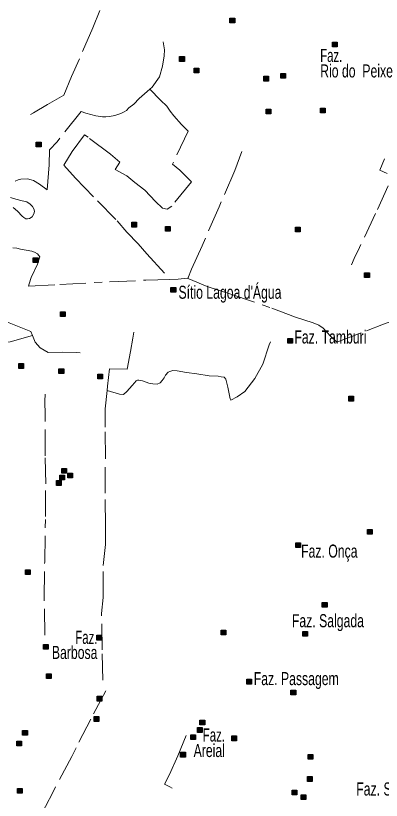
# Model space of a CAD drawing. Extents: x 445.6 to 500, y 8618.1 to 8673.4.
# Drawn here: x 480.73 to 485.21, y 8658.81 to 8668.42 of the extents above; entities that cross this region are included whole.
import ezdxf
from ezdxf.enums import TextEntityAlignment as Align

# ---------------------------------------------------------------- set-up
doc = ezdxf.new("R2010")
doc.units = 0
doc.header["$LTSCALE"] = 0.064
doc.linetypes.add('DOT_DASHED', pattern=[7.7, 5, -1.2, 0.3, -1.2])
doc.layers.add('2', color=7, linetype='Continuous', lineweight=25)
doc.layers.add('22', color=7, linetype='DOT_DASHED', lineweight=13)
doc.layers.add('61', color=7, linetype='Continuous')

msp = doc.modelspace()

# ---------------------------------------------------------------- hatches: boundary and pattern name
at = {"layer": '2'}
for points in [[(483.3572, 8668.3929), (483.4152, 8668.3929), (483.4152, 8668.3349), (483.3572, 8668.3349)], [(484.6131, 8668.0979), (484.6711, 8668.0979), (484.6711, 8668.0399), (484.6131, 8668.0399)], [(482.7407, 8667.9212), (482.7987, 8667.9212), (482.7987, 8667.8632), (482.7407, 8667.8632)], [(482.9197, 8667.7822), (482.9777, 8667.7822), (482.9777, 8667.7242), (482.9197, 8667.7242)], [(483.771, 8667.6806), (483.829, 8667.6806), (483.829, 8667.6226), (483.771, 8667.6226)], [(483.9804, 8667.7145), (484.0384, 8667.7145), (484.0384, 8667.6565), (483.9804, 8667.6565)], [(483.8014, 8667.2774), (483.8594, 8667.2774), (483.8594, 8667.2194), (483.8014, 8667.2194)], [(484.4646, 8667.2911), (484.5226, 8667.2911), (484.5226, 8667.2331), (484.4646, 8667.2331)], [(480.9857, 8666.8743), (481.0437, 8666.8743), (481.0437, 8666.8163), (480.9857, 8666.8163)], [(482.1561, 8665.8922), (482.2141, 8665.8922), (482.2141, 8665.8342), (482.1561, 8665.8342)], [(482.5671, 8665.8413), (482.6251, 8665.8413), (482.6251, 8665.7833), (482.5671, 8665.7833)], [(484.1581, 8665.8345), (484.2161, 8665.8345), (484.2161, 8665.7765), (484.1581, 8665.7765)], [(480.949, 8665.4585), (481.007, 8665.4585), (481.007, 8665.4005), (480.949, 8665.4005)], [(485.0065, 8665.2722), (485.0645, 8665.2722), (485.0645, 8665.2142), (485.0065, 8665.2142)], [(482.6347, 8665.0925), (482.6927, 8665.0925), (482.6927, 8665.0345), (482.6347, 8665.0345)], [(481.2812, 8664.7945), (481.3392, 8664.7945), (481.3392, 8664.7365), (481.2812, 8664.7365)], [(484.0668, 8664.4691), (484.1248, 8664.4691), (484.1248, 8664.4111), (484.0668, 8664.4111)], [(480.77, 8664.1608), (480.828, 8664.1608), (480.828, 8664.1028), (480.77, 8664.1028)], [(481.2632, 8664.0972), (481.3212, 8664.0972), (481.3212, 8664.0392), (481.2632, 8664.0392)], [(481.7384, 8664.032), (481.7964, 8664.032), (481.7964, 8663.974), (481.7384, 8663.974)], [(484.8128, 8663.7609), (484.8708, 8663.7609), (484.8708, 8663.7029), (484.8128, 8663.7029)], [(481.2967, 8662.8767), (481.3547, 8662.8767), (481.3547, 8662.8187), (481.2967, 8662.8187)], [(481.2731, 8662.7954), (481.3311, 8662.7954), (481.3311, 8662.7374), (481.2731, 8662.7374)], [(481.371, 8662.8191), (481.429, 8662.8191), (481.429, 8662.7611), (481.371, 8662.7611)], [(481.2325, 8662.7276), (481.2905, 8662.7276), (481.2905, 8662.6696), (481.2325, 8662.6696)], [(485.0427, 8662.1296), (485.1007, 8662.1296), (485.1007, 8662.0716), (485.0427, 8662.0716)], [(484.1636, 8661.9648), (484.2216, 8661.9648), (484.2216, 8661.9068), (484.1636, 8661.9068)], [(480.8536, 8661.6359), (480.9116, 8661.6359), (480.9116, 8661.5779), (480.8536, 8661.5779)], [(484.4878, 8661.2364), (484.5458, 8661.2364), (484.5458, 8661.1784), (484.4878, 8661.1784)], [(481.7251, 8660.833), (481.7831, 8660.833), (481.7831, 8660.775), (481.7251, 8660.775)], [(483.2491, 8660.8976), (483.3071, 8660.8976), (483.3071, 8660.8396), (483.2491, 8660.8396)], [(484.248, 8660.8807), (484.306, 8660.8807), (484.306, 8660.8227), (484.248, 8660.8227)], [(481.0732, 8660.7212), (481.1312, 8660.7212), (481.1312, 8660.6632), (481.0732, 8660.6632)], [(481.1103, 8660.3621), (481.1683, 8660.3621), (481.1683, 8660.3041), (481.1103, 8660.3041)], [(483.5641, 8660.2937), (483.6221, 8660.2937), (483.6221, 8660.2357), (483.5641, 8660.2357)], [(484.1046, 8660.1616), (484.1626, 8660.1616), (484.1626, 8660.1036), (484.1046, 8660.1036)], [(481.7296, 8660.086), (481.7876, 8660.086), (481.7876, 8660.028), (481.7296, 8660.028)], [(481.6955, 8659.8367), (481.7535, 8659.8367), (481.7535, 8659.7787), (481.6955, 8659.7787)], [(482.9901, 8659.793), (483.0481, 8659.793), (483.0481, 8659.735), (482.9901, 8659.735)], [(482.9597, 8659.7015), (483.0177, 8659.7015), (483.0177, 8659.6435), (482.9597, 8659.6435)], [(480.8185, 8659.6673), (480.8765, 8659.6673), (480.8765, 8659.6093), (480.8185, 8659.6093)], [(482.8786, 8659.6135), (482.9366, 8659.6135), (482.9366, 8659.5555), (482.8786, 8659.5555)], [(483.3785, 8659.5999), (483.4365, 8659.5999), (483.4365, 8659.5419), (483.3785, 8659.5419)], [(480.7475, 8659.5351), (480.8055, 8659.5351), (480.8055, 8659.4771), (480.7475, 8659.4771)], [(482.7536, 8659.4), (482.8116, 8659.4), (482.8116, 8659.342), (482.7536, 8659.342)], [(484.3142, 8659.3729), (484.3722, 8659.3729), (484.3722, 8659.3149), (484.3142, 8659.3149)], [(484.3074, 8659.1019), (484.3654, 8659.1019), (484.3654, 8659.0439), (484.3074, 8659.0439)], [(480.7543, 8658.9558), (480.8123, 8658.9558), (480.8123, 8658.8978), (480.7543, 8658.8978)], [(484.1183, 8658.9359), (484.1763, 8658.9359), (484.1763, 8658.8779), (484.1183, 8658.8779)], [(484.2297, 8658.8783), (484.2877, 8658.8783), (484.2877, 8658.8203), (484.2297, 8658.8203)]]:
    msp.add_hatch(color=256, dxfattribs=at).paths.add_polyline_path(points)

# ---------------------------------------------------------------- linework, layer by layer
for points in [[(483.3572, 8668.3929), (483.4152, 8668.3929), (483.4152, 8668.3349), (483.3572, 8668.3349)], [(484.6131, 8668.0979), (484.6711, 8668.0979), (484.6711, 8668.0399), (484.6131, 8668.0399)], [(482.7407, 8667.9212), (482.7987, 8667.9212), (482.7987, 8667.8632), (482.7407, 8667.8632)], [(482.9197, 8667.7822), (482.9777, 8667.7822), (482.9777, 8667.7242), (482.9197, 8667.7242)], [(483.771, 8667.6806), (483.829, 8667.6806), (483.829, 8667.6226), (483.771, 8667.6226)], [(483.9804, 8667.7145), (484.0384, 8667.7145), (484.0384, 8667.6565), (483.9804, 8667.6565)], [(483.8014, 8667.2774), (483.8594, 8667.2774), (483.8594, 8667.2194), (483.8014, 8667.2194)], [(484.4646, 8667.2911), (484.5226, 8667.2911), (484.5226, 8667.2331), (484.4646, 8667.2331)], [(480.9857, 8666.8743), (481.0437, 8666.8743), (481.0437, 8666.8163), (480.9857, 8666.8163)], [(482.1561, 8665.8922), (482.2141, 8665.8922), (482.2141, 8665.8342), (482.1561, 8665.8342)], [(482.5671, 8665.8413), (482.6251, 8665.8413), (482.6251, 8665.7833), (482.5671, 8665.7833)], [(484.1581, 8665.8345), (484.2161, 8665.8345), (484.2161, 8665.7765), (484.1581, 8665.7765)], [(480.949, 8665.4585), (481.007, 8665.4585), (481.007, 8665.4005), (480.949, 8665.4005)], [(485.0065, 8665.2722), (485.0645, 8665.2722), (485.0645, 8665.2142), (485.0065, 8665.2142)], [(482.6347, 8665.0925), (482.6927, 8665.0925), (482.6927, 8665.0345), (482.6347, 8665.0345)], [(481.2812, 8664.7945), (481.3392, 8664.7945), (481.3392, 8664.7365), (481.2812, 8664.7365)], [(484.0668, 8664.4691), (484.1248, 8664.4691), (484.1248, 8664.4111), (484.0668, 8664.4111)], [(480.77, 8664.1608), (480.828, 8664.1608), (480.828, 8664.1028), (480.77, 8664.1028)], [(481.2632, 8664.0972), (481.3212, 8664.0972), (481.3212, 8664.0392), (481.2632, 8664.0392)], [(481.7384, 8664.032), (481.7964, 8664.032), (481.7964, 8663.974), (481.7384, 8663.974)], [(484.8128, 8663.7609), (484.8708, 8663.7609), (484.8708, 8663.7029), (484.8128, 8663.7029)], [(481.2967, 8662.8767), (481.3547, 8662.8767), (481.3547, 8662.8187), (481.2967, 8662.8187)], [(481.2731, 8662.7954), (481.3311, 8662.7954), (481.3311, 8662.7374), (481.2731, 8662.7374)], [(481.371, 8662.8191), (481.429, 8662.8191), (481.429, 8662.7611), (481.371, 8662.7611)], [(481.2325, 8662.7276), (481.2905, 8662.7276), (481.2905, 8662.6696), (481.2325, 8662.6696)], [(485.0427, 8662.1296), (485.1007, 8662.1296), (485.1007, 8662.0716), (485.0427, 8662.0716)], [(484.1636, 8661.9648), (484.2216, 8661.9648), (484.2216, 8661.9068), (484.1636, 8661.9068)], [(480.8536, 8661.6359), (480.9116, 8661.6359), (480.9116, 8661.5779), (480.8536, 8661.5779)], [(484.4878, 8661.2364), (484.5458, 8661.2364), (484.5458, 8661.1784), (484.4878, 8661.1784)], [(481.7251, 8660.833), (481.7831, 8660.833), (481.7831, 8660.775), (481.7251, 8660.775)], [(483.2491, 8660.8976), (483.3071, 8660.8976), (483.3071, 8660.8396), (483.2491, 8660.8396)], [(484.248, 8660.8807), (484.306, 8660.8807), (484.306, 8660.8227), (484.248, 8660.8227)], [(481.0732, 8660.7212), (481.1312, 8660.7212), (481.1312, 8660.6632), (481.0732, 8660.6632)], [(481.1103, 8660.3621), (481.1683, 8660.3621), (481.1683, 8660.3041), (481.1103, 8660.3041)], [(483.5641, 8660.2937), (483.6221, 8660.2937), (483.6221, 8660.2357), (483.5641, 8660.2357)], [(484.1046, 8660.1616), (484.1626, 8660.1616), (484.1626, 8660.1036), (484.1046, 8660.1036)], [(481.7296, 8660.086), (481.7876, 8660.086), (481.7876, 8660.028), (481.7296, 8660.028)], [(481.6955, 8659.8367), (481.7535, 8659.8367), (481.7535, 8659.7787), (481.6955, 8659.7787)], [(482.9901, 8659.793), (483.0481, 8659.793), (483.0481, 8659.735), (482.9901, 8659.735)], [(482.9597, 8659.7015), (483.0177, 8659.7015), (483.0177, 8659.6435), (482.9597, 8659.6435)], [(480.8185, 8659.6673), (480.8765, 8659.6673), (480.8765, 8659.6093), (480.8185, 8659.6093)], [(482.8786, 8659.6135), (482.9366, 8659.6135), (482.9366, 8659.5555), (482.8786, 8659.5555)], [(483.3785, 8659.5999), (483.4365, 8659.5999), (483.4365, 8659.5419), (483.3785, 8659.5419)], [(480.7475, 8659.5351), (480.8055, 8659.5351), (480.8055, 8659.4771), (480.7475, 8659.4771)], [(482.7536, 8659.4), (482.8116, 8659.4), (482.8116, 8659.342), (482.7536, 8659.342)], [(484.3142, 8659.3729), (484.3722, 8659.3729), (484.3722, 8659.3149), (484.3142, 8659.3149)], [(484.3074, 8659.1019), (484.3654, 8659.1019), (484.3654, 8659.0439), (484.3074, 8659.0439)], [(480.7543, 8658.9558), (480.8123, 8658.9558), (480.8123, 8658.8978), (480.7543, 8658.8978)], [(484.1183, 8658.9359), (484.1763, 8658.9359), (484.1763, 8658.8779), (484.1183, 8658.8779)], [(484.2297, 8658.8783), (484.2877, 8658.8783), (484.2877, 8658.8203), (484.2297, 8658.8203)]]:
    msp.add_lwpolyline(points, close=True, dxfattribs=at)
at = {"layer": '22'}
for points in [[(481.9125, 8668.8421), (481.7624, 8668.4852), (481.6795, 8668.2757), (481.5132, 8667.8965), (481.4174, 8667.6792), (481.3211, 8667.4503), (481.1217, 8667.3365), (480.9508, 8667.2331), (480.915, 8667.2121)], [(482.5414, 8668.1012), (482.5566, 8668.0063), (482.5526, 8667.9297), (482.5324, 8667.8047), (482.4961, 8667.6757), (482.4032, 8667.5467), (482.3763, 8667.5233)], [(482.3763, 8667.5233), (482.2458, 8667.4096), (482.1812, 8667.3411), (482.1207, 8667.2927), (482.0884, 8667.2605), (482.0601, 8667.2443), (482.0198, 8667.2242), (481.9592, 8667.204), (481.9269, 8667.196), (481.8785, 8667.1879), (481.8381, 8667.1839), (481.7978, 8667.1839), (481.713, 8667.196), (481.5909, 8667.231), (481.5344, 8667.2511), (481.2397, 8666.8762), (481.1469, 8666.7794), (481.1429, 8666.598), (481.1185, 8666.2889), (481.0256, 8666.3574), (480.953, 8666.4058), (480.9247, 8666.4139), (480.8763, 8666.426), (480.7955, 8666.4219), (480.7632, 8666.4139), (480.7269, 8666.3977)], [(482.3763, 8667.5233), (482.5062, 8667.3868), (482.583, 8667.3128), (482.6257, 8667.2531), (482.6712, 8667.1963), (482.7652, 8667.0911), (482.8449, 8667.0087), (482.6542, 8666.605), (482.7452, 8666.5311), (482.8855, 8666.3874), (482.6436, 8666.0889), (482.5867, 8666.0519), (482.5326, 8666.0633), (482.4444, 8666.1486), (482.315, 8666.2847), (482.1927, 8666.3813), (482.0959, 8666.4609), (481.9534, 8666.5382), (482.0074, 8666.6292), (481.8936, 8666.7258), (481.6204, 8666.9333), (481.5772, 8666.9628), (481.4235, 8666.7581), (481.3211, 8666.5904), (481.4662, 8666.4341), (481.7341, 8666.1535), (481.976, 8665.9091), (482.0927, 8665.7726), (482.2322, 8665.6276), (482.3413, 8665.5065), (482.6229, 8665.1916)], [(483.5025, 8666.7603), (483.4171, 8666.5274), (483.2247, 8666.081), (483.0161, 8665.6047), (482.8857, 8665.3195), (482.8421, 8665.2039)], [(485.2503, 8666.6703), (485.1911, 8666.5301), (485.2815, 8666.4896)], [(485.294, 8666.3401), (485.1406, 8665.9984), (484.9434, 8665.5826), (484.8779, 8665.4486), (484.8436, 8665.3707)], [(480.6704, 8666.1962), (480.735, 8666.176), (480.8117, 8666.1558), (480.8682, 8666.1437), (480.9126, 8666.1155), (480.9409, 8666.0873), (480.957, 8666.0551), (480.9651, 8666.0268), (480.961, 8666.0067), (480.953, 8665.9865), (480.9368, 8665.9583), (480.9045, 8665.9381), (480.8763, 8665.9341), (480.8561, 8665.9341), (480.8319, 8665.9502), (480.8117, 8665.9664), (480.7552, 8666.0268), (480.7027, 8666.0752)], [(480.0981, 8665.8986), (480.0473, 8665.8445), (479.7839, 8665.5596), (479.6884, 8665.4575), (479.8043, 8665.3315), (480.0953, 8665.0978), (480.2454, 8664.9411), (480.3477, 8664.8151), (480.4227, 8664.7368), (480.6546, 8664.6619), (480.9207, 8664.5563), (480.9408, 8664.5057)], [(480.6975, 8665.5778), (480.746, 8665.5738), (480.7944, 8665.5617), (480.9316, 8665.5375), (480.9639, 8665.5254), (481.0002, 8665.5052), (481.0164, 8665.4851), (481.0285, 8665.469), (481.0002, 8665.3803), (480.9236, 8665.215), (480.9004, 8665.1396), (480.8913, 8665.1102), (481.2747, 8665.1303), (481.8802, 8665.1626), (482.3282, 8665.1827), (482.6229, 8665.1916)], [(482.6229, 8665.1916), (482.7223, 8665.1946), (482.8353, 8665.2067), (482.8421, 8665.2039)], [(482.8421, 8665.2039), (482.8548, 8665.1986), (483.0775, 8665.1059), (483.356, 8665.0172), (483.8687, 8664.8398), (484.1616, 8664.7286), (484.3756, 8664.6601), (484.4443, 8664.6318), (484.4975, 8664.5968), (484.5881, 8664.497), (484.6648, 8664.425), (485.0274, 8664.5643), (485.2388, 8664.6432), (485.4341, 8664.7152), (485.4991, 8664.7453), (485.6758, 8664.7871), (486.0025, 8664.848), (486.3349, 8664.9223), (486.4836, 8664.9595), (486.6951, 8665.0012), (487.1311, 8665.0922), (487.2961, 8665.1294), (487.3542, 8665.1433)], [(480.9408, 8664.5057), (480.6646, 8664.4267), (480.182, 8664.4198), (480.0581, 8664.3435), (479.9887, 8664.3418), (479.928, 8664.3574), (479.8083, 8664.3679)], [(480.9408, 8664.5057), (480.9727, 8664.4253), (481.0341, 8664.3537), (481.1296, 8664.2992), (481.307, 8664.3026), (481.4775, 8664.2992), (481.5231, 8664.2946)], [(481.854, 8663.8335), (481.8596, 8663.8838), (481.8813, 8664.0973), (482.0983, 8664.0942), (482.1385, 8664.3078), (482.1695, 8664.4719), (482.179, 8664.548)], [(481.854, 8663.8335), (482.0055, 8663.7874), (482.052, 8663.7813), (482.0954, 8663.8184), (482.1604, 8663.8927), (482.1883, 8663.9267), (482.21, 8663.9484), (482.2255, 8663.9577), (482.241, 8663.9577), (482.2596, 8663.9546), (482.2844, 8663.9484), (482.3619, 8663.9205), (482.4115, 8663.9144), (482.4673, 8663.9082), (482.5044, 8663.9267), (482.5292, 8663.9546), (482.5509, 8663.9886), (482.5664, 8664.0196), (482.6005, 8664.0567), (482.6191, 8664.066), (482.6563, 8664.0753), (482.7121, 8664.0722), (482.8236, 8664.0536), (482.9507, 8664.0351), (483.1026, 8664.0134), (483.211, 8664.0072), (483.25, 8664.0009), (483.2872, 8663.9947), (483.3058, 8663.9699), (483.3306, 8663.874), (483.3585, 8663.7316), (483.3678, 8663.713), (483.4452, 8663.7533), (483.5413, 8663.8214), (483.6622, 8663.9792), (483.7613, 8664.1556), (483.8362, 8664.3892), (483.8521, 8664.427)], [(481.8004, 8660.2851), (481.7911, 8660.6535), (481.7849, 8661.0992), (481.8035, 8661.2942), (481.8037, 8661.6863), (481.8316, 8661.9463), (481.8347, 8662.1754), (481.8286, 8662.5741), (481.8317, 8663.0074), (481.8286, 8663.3808), (481.8286, 8663.6067), (481.854, 8663.8335)], [(481.0914, 8660.8364), (481.0823, 8661.2926), (481.0885, 8661.7313), (481.0978, 8662.2865), (481.1009, 8662.688), (481.0949, 8663.0332), (481.0949, 8663.5336), (481.0918, 8663.7025), (481.0941, 8663.7888)], [(481.8377, 8660.1516), (481.6543, 8659.8071), (481.474, 8659.4563), (481.4212, 8659.3477), (481.1906, 8658.9173), (481.0974, 8658.7372), (481.0539, 8658.6503)], [(482.8216, 8659.6069), (482.7207, 8659.3575), (482.6168, 8659.1264), (482.5574, 8659.0108), (482.6227, 8658.9752), (482.6511, 8658.9594)]]:
    msp.add_lwpolyline(points, dxfattribs=at)

# ---------------------------------------------------------------- texts
at = {"layer": '61'}
for s, width, p in [('Faz.', 0.65, (484.4623, 8667.8564)), ('Rio do  Peixe', 0.7, (484.4623, 8667.6664)), ("Sítio Lagoa d'Água", 0.7, (482.7269, 8664.9554)), ('Faz. Tamburi', 0.7, (484.1461, 8664.4074)), ('Faz. Onça', 0.7, (484.2285, 8661.7846)), ('Faz. Salgada', 0.7, (484.1158, 8660.9318)), ('Faz. Passagem', 0.7, (483.649, 8660.2226)), ('Faz. Santa Cruz', 0.7, (484.9038, 8658.8704))]:
    msp.add_text(s, height=0.16, dxfattribs=dict(at, width=width)).set_placement(p)
for s, width, p in [('Faz.', 0.65, (481.7345, 8660.7279)), ('Barbosa', 0.7, (481.7345, 8660.5429)), ('Faz.', 0.65, (483.2954, 8659.5316)), ('Areial', 0.7, (483.2954, 8659.3416))]:
    msp.add_text(s, height=0.16, dxfattribs=dict(at, width=width)).set_placement(p, align=Align.RIGHT)

doc.saveas('drawing.dxf')
